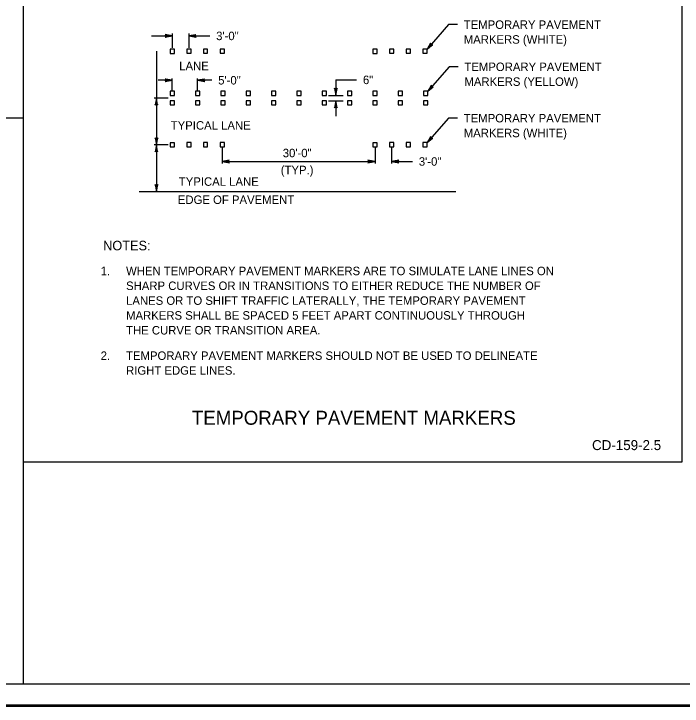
# Model space of a CAD drawing. Extents: x 499940 to 501012, y 499990 to 500649.
# Drawn here: x 500335 to 500650.7, y 499989.5 to 500316.4 of the extents above; entities that cross this region are included whole.
import ezdxf

# ---------------------------------------------------------------- set-up
doc = ezdxf.new("R2010")
doc.units = 0
for name, color, linetype in [('1', 7, 'Continuous'), ('10', 7, 'Continuous'), ('24', 7, 'Continuous'), ('3', 7, 'Continuous'), ('39', 7, 'Continuous'), ('41', 7, 'Continuous'), ('5', 7, 'Continuous'), ('60', 7, 'Continuous')]:
    doc.layers.add(name, color=color, linetype=linetype)

msp = doc.modelspace()

# ---------------------------------------------------------------- linework, layer by layer
at = {"layer": '1'}
for p, q in [((500000, 500000), (500990, 500000)), ((499946.96, 499989.52), (501012.44, 499989.52))]:
    msp.add_line(p, q, dxfattribs=at)
at = {"layer": '10'}
for p, q in [((500339.52, 500000), (500339.52, 500630)), ((500650.61, 500104.92), (500650.61, 500630)), ((500000, 500267.34), (500339.52, 500267.34)), ((500339.52, 500104.92), (500650.61, 500104.92))]:
    msp.add_line(p, q, dxfattribs=at)
at = {"layer": '24'}
for points in [[(500409.84, 500306.02), (500406.51, 500306.61), (500407.31, 500306.02), (500406.53, 500305.45), (500409.84, 500306.02), (500409.62, 500306.02), (500406.61, 500306.57), (500407.37, 500306.02), (500406.67, 500305.49), (500409.5, 500306.01), (500409.39, 500306.02), (500406.81, 500306.48), (500407.39, 500306.02), (500406.79, 500305.57), (500409.34, 500306.02), (500409.23, 500306.01), (500406.97, 500306.41), (500407.41, 500306.02), (500406.96, 500305.62), (500408.9, 500306.01), (500408.72, 500306.01), (500407.14, 500306.33), (500407.45, 500306.03), (500407.12, 500305.7), (500408.68, 500306.02), (500408.51, 500306.03), (500407.32, 500306.24), (500407.55, 500306.01), (500407.3, 500305.78), (500408.34, 500306.02), (500408.18, 500306.04), (500407.46, 500306.18), (500407.58, 500306.02), (500407.39, 500305.84), (500408.09, 500306.02), (500407.62, 500306.13), (500407.69, 500306.01), (500407.49, 500305.88), (500407.97, 500306.01), (500407.67, 500306.08), (500407.79, 500305.98), (500407.65, 500305.92), (500407.79, 500306.02), (500407.72, 500306.03)], [(500417.71, 500306.02), (500421.04, 500305.44), (500420.24, 500306.02), (500421.02, 500306.6), (500417.71, 500306.02), (500417.93, 500306.03), (500420.94, 500305.48), (500420.18, 500306.03), (500420.88, 500306.56), (500418.05, 500306.04), (500418.16, 500306.02), (500420.74, 500305.57), (500420.16, 500306.03), (500420.76, 500306.48), (500418.21, 500306.02), (500418.32, 500306.04), (500420.58, 500305.63), (500420.14, 500306.02), (500420.59, 500306.43), (500418.64, 500306.04), (500418.83, 500306.04), (500420.41, 500305.72), (500420.1, 500306.02), (500420.43, 500306.35), (500418.87, 500306.02), (500419.04, 500306.01), (500420.23, 500305.81), (500420, 500306.04), (500420.25, 500306.27), (500419.21, 500306.02), (500419.37, 500306.01), (500420.09, 500305.87), (500419.97, 500306.03), (500420.16, 500306.21), (500419.46, 500306.02), (500419.92, 500305.91), (500419.86, 500306.04), (500420.06, 500306.17), (500419.58, 500306.04), (500419.88, 500305.96), (500419.75, 500306.06), (500419.9, 500306.13), (500419.75, 500306.03), (500419.83, 500306.02)], [(500530.19, 500299.83), (500532.78, 500301.91), (500531.83, 500301.7), (500531.91, 500302.66), (500530.19, 500299.83), (500530.33, 500300), (500532.69, 500301.87), (500531.79, 500301.66), (500531.86, 500302.53), (500530.4, 500300.09), (500530.48, 500300.16), (500532.5, 500301.78), (500531.78, 500301.65), (500531.83, 500302.38), (500530.52, 500300.2), (500530.58, 500300.29), (500532.34, 500301.7), (500531.77, 500301.63), (500531.76, 500302.22), (500530.78, 500300.53), (500530.91, 500300.67), (500532.17, 500301.63), (500531.75, 500301.6), (500531.72, 500302.05), (500530.94, 500300.68), (500531.06, 500300.81), (500531.98, 500301.56), (500531.67, 500301.54), (500531.66, 500301.87), (500531.16, 500300.94), (500531.28, 500301.05), (500531.85, 500301.49), (500531.65, 500301.51), (500531.65, 500301.77), (500531.33, 500301.12), (500531.71, 500301.4), (500531.57, 500301.43), (500531.61, 500301.66), (500531.39, 500301.22), (500531.64, 500301.4), (500531.49, 500301.37), (500531.54, 500301.52), (500531.51, 500301.35), (500531.57, 500301.39)], [(500409.84, 500285.08), (500406.51, 500285.67), (500407.31, 500285.08), (500406.53, 500284.5), (500409.84, 500285.08), (500409.62, 500285.08), (500406.61, 500285.63), (500407.37, 500285.07), (500406.67, 500284.55), (500409.5, 500285.06), (500409.39, 500285.08), (500406.81, 500285.54), (500407.39, 500285.07), (500406.79, 500284.62), (500409.34, 500285.08), (500409.23, 500285.06), (500406.97, 500285.47), (500407.41, 500285.08), (500406.96, 500284.68), (500408.9, 500285.06), (500408.72, 500285.06), (500407.14, 500285.39), (500407.45, 500285.09), (500407.12, 500284.76), (500408.68, 500285.08), (500408.51, 500285.09), (500407.32, 500285.29), (500407.55, 500285.06), (500407.3, 500284.84), (500408.34, 500285.08), (500408.18, 500285.1), (500407.46, 500285.23), (500407.58, 500285.07), (500407.39, 500284.9), (500408.09, 500285.08), (500407.62, 500285.19), (500407.69, 500285.06), (500407.49, 500284.94), (500407.97, 500285.06), (500407.67, 500285.14), (500407.79, 500285.04), (500407.65, 500284.98), (500407.79, 500285.07), (500407.72, 500285.09)], [(500421.81, 500285.08), (500425.13, 500284.49), (500424.34, 500285.08), (500425.11, 500285.66), (500421.81, 500285.08), (500422.03, 500285.09), (500425.04, 500284.54), (500424.27, 500285.09), (500424.98, 500285.61), (500422.15, 500285.1), (500422.26, 500285.08), (500424.84, 500284.62), (500424.26, 500285.09), (500424.85, 500285.54), (500422.31, 500285.08), (500422.42, 500285.1), (500424.67, 500284.69), (500424.23, 500285.08), (500424.68, 500285.49), (500422.74, 500285.1), (500422.93, 500285.1), (500424.5, 500284.78), (500424.2, 500285.07), (500424.53, 500285.4), (500422.96, 500285.08), (500423.14, 500285.07), (500424.32, 500284.87), (500424.1, 500285.1), (500424.34, 500285.33), (500423.3, 500285.08), (500423.47, 500285.06), (500424.18, 500284.93), (500424.06, 500285.09), (500424.26, 500285.27), (500423.55, 500285.08), (500424.02, 500284.97), (500423.95, 500285.1), (500424.16, 500285.23), (500423.67, 500285.1), (500423.98, 500285.02), (500423.85, 500285.12), (500424, 500285.18), (500423.85, 500285.09), (500423.93, 500285.07)], [(500487.06, 500277.93), (500487.65, 500281.28), (500487.06, 500280.48), (500486.48, 500281.27), (500487.06, 500277.93), (500487.06, 500278.16), (500487.61, 500281.19), (500487.05, 500280.42), (500486.52, 500281.13), (500487.04, 500278.28), (500487.06, 500278.39), (500487.52, 500280.99), (500487.05, 500280.4), (500486.6, 500281), (500487.06, 500278.44), (500487.04, 500278.55), (500487.45, 500280.82), (500487.06, 500280.38), (500486.65, 500280.83), (500487.04, 500278.87), (500487.04, 500279.06), (500487.37, 500280.65), (500487.07, 500280.34), (500486.74, 500280.68), (500487.06, 500279.1), (500487.07, 500279.28), (500487.28, 500280.47), (500487.04, 500280.24), (500486.81, 500280.49), (500487.06, 500279.44), (500487.08, 500279.61), (500487.22, 500280.33), (500487.05, 500280.21), (500486.88, 500280.4), (500487.06, 500279.7), (500487.17, 500280.16), (500487.04, 500280.1), (500486.92, 500280.3), (500487.04, 500279.81), (500487.12, 500280.12), (500487.02, 500279.99), (500486.96, 500280.14), (500487.05, 500279.99), (500487.07, 500280.07)], [(500530.51, 500279.9), (500533.1, 500281.98), (500532.15, 500281.78), (500532.22, 500282.73), (500530.51, 500279.9), (500530.65, 500280.07), (500533.01, 500281.94), (500532.1, 500281.74), (500532.17, 500282.6), (500530.72, 500280.16), (500530.8, 500280.24), (500532.81, 500281.85), (500532.09, 500281.72), (500532.14, 500282.46), (500530.83, 500280.27), (500530.89, 500280.37), (500532.66, 500281.77), (500532.08, 500281.7), (500532.07, 500282.3), (500531.1, 500280.6), (500531.22, 500280.74), (500532.49, 500281.7), (500532.07, 500281.67), (500532.04, 500282.13), (500531.26, 500280.76), (500531.38, 500280.88), (500532.3, 500281.63), (500531.98, 500281.61), (500531.97, 500281.94), (500531.48, 500281.01), (500531.6, 500281.12), (500532.16, 500281.56), (500531.97, 500281.58), (500531.96, 500281.84), (500531.64, 500281.2), (500532.02, 500281.47), (500531.89, 500281.5), (500531.92, 500281.74), (500531.7, 500281.3), (500531.96, 500281.47), (500531.8, 500281.44), (500531.85, 500281.59), (500531.83, 500281.42), (500531.89, 500281.47)], [(500402.34, 500276.65), (500401.75, 500273.33), (500402.34, 500274.12), (500402.92, 500273.35), (500402.34, 500276.65), (500402.35, 500276.43), (500401.8, 500273.42), (500402.35, 500274.19), (500402.87, 500273.48), (500402.36, 500276.31), (500402.34, 500276.2), (500401.88, 500273.62), (500402.35, 500274.2), (500402.8, 500273.61), (500402.34, 500276.15), (500402.36, 500276.04), (500401.95, 500273.79), (500402.34, 500274.23), (500402.74, 500273.78), (500402.36, 500275.72), (500402.36, 500275.53), (500402.03, 500273.96), (500402.33, 500274.26), (500402.66, 500273.93), (500402.34, 500275.5), (500402.33, 500275.32), (500402.13, 500274.14), (500402.36, 500274.36), (500402.58, 500274.12), (500402.34, 500275.16), (500402.32, 500274.99), (500402.19, 500274.28), (500402.35, 500274.4), (500402.52, 500274.2), (500402.34, 500274.91), (500402.23, 500274.44), (500402.36, 500274.51), (500402.48, 500274.3), (500402.36, 500274.79), (500402.28, 500274.48), (500402.38, 500274.61), (500402.44, 500274.47), (500402.35, 500274.61), (500402.33, 500274.53)], [(500487.06, 500275.38), (500486.47, 500272.03), (500487.06, 500272.83), (500487.64, 500272.05), (500487.06, 500275.38), (500487.07, 500275.16), (500486.51, 500272.13), (500487.07, 500272.9), (500487.6, 500272.19), (500487.08, 500275.04), (500487.06, 500274.93), (500486.6, 500272.33), (500487.07, 500272.91), (500487.52, 500272.31), (500487.06, 500274.88), (500487.08, 500274.77), (500486.67, 500272.49), (500487.06, 500272.94), (500487.47, 500272.49), (500487.08, 500274.44), (500487.08, 500274.25), (500486.75, 500272.66), (500487.05, 500272.97), (500487.38, 500272.64), (500487.06, 500274.22), (500487.05, 500274.04), (500486.85, 500272.85), (500487.08, 500273.08), (500487.31, 500272.83), (500487.06, 500273.88), (500487.04, 500273.71), (500486.91, 500272.99), (500487.07, 500273.11), (500487.25, 500272.91), (500487.06, 500273.62), (500486.95, 500273.15), (500487.08, 500273.22), (500487.21, 500273.01), (500487.08, 500273.5), (500487, 500273.2), (500487.1, 500273.32), (500487.16, 500273.18), (500487.07, 500273.32), (500487.05, 500273.25)], [(500402.34, 500254.57), (500402.93, 500257.89), (500402.34, 500257.1), (500401.76, 500257.87), (500402.34, 500254.57), (500402.33, 500254.79), (500402.88, 500257.8), (500402.33, 500257.04), (500401.81, 500257.74), (500402.32, 500254.91), (500402.34, 500255.02), (500402.8, 500257.6), (500402.33, 500257.02), (500401.88, 500257.61), (500402.34, 500255.07), (500402.32, 500255.18), (500402.73, 500257.43), (500402.34, 500256.99), (500401.93, 500257.44), (500402.32, 500255.5), (500402.32, 500255.69), (500402.65, 500257.27), (500402.35, 500256.96), (500402.02, 500257.29), (500402.34, 500255.72), (500402.35, 500255.9), (500402.55, 500257.09), (500402.32, 500256.86), (500402.09, 500257.1), (500402.34, 500256.06), (500402.36, 500256.23), (500402.49, 500256.94), (500402.33, 500256.82), (500402.15, 500257.02), (500402.34, 500256.32), (500402.45, 500256.78), (500402.32, 500256.71), (500402.19, 500256.92), (500402.32, 500256.43), (500402.4, 500256.74), (500402.3, 500256.61), (500402.24, 500256.76), (500402.33, 500256.61), (500402.35, 500256.69)], [(500530.19, 500255.66), (500532.78, 500257.74), (500531.83, 500257.53), (500531.91, 500258.48), (500530.19, 500255.66), (500530.33, 500255.82), (500532.69, 500257.7), (500531.79, 500257.49), (500531.86, 500258.35), (500530.4, 500255.92), (500530.48, 500255.99), (500532.5, 500257.6), (500531.78, 500257.48), (500531.83, 500258.21), (500530.52, 500256.03), (500530.58, 500256.12), (500532.34, 500257.53), (500531.77, 500257.45), (500531.76, 500258.05), (500530.78, 500256.36), (500530.91, 500256.5), (500532.17, 500257.46), (500531.75, 500257.42), (500531.72, 500257.88), (500530.94, 500256.51), (500531.06, 500256.64), (500531.98, 500257.38), (500531.67, 500257.36), (500531.66, 500257.69), (500531.16, 500256.76), (500531.28, 500256.88), (500531.85, 500257.32), (500531.65, 500257.33), (500531.65, 500257.59), (500531.33, 500256.95), (500531.71, 500257.22), (500531.57, 500257.26), (500531.61, 500257.49), (500531.39, 500257.05), (500531.64, 500257.23), (500531.49, 500257.2), (500531.54, 500257.34), (500531.51, 500257.18), (500531.57, 500257.22)], [(500402.34, 500254.57), (500401.75, 500251.24), (500402.34, 500252.04), (500402.92, 500251.26), (500402.34, 500254.57), (500402.35, 500254.35), (500401.8, 500251.34), (500402.35, 500252.1), (500402.87, 500251.4), (500402.36, 500254.23), (500402.34, 500254.12), (500401.88, 500251.54), (500402.35, 500252.12), (500402.8, 500251.52), (500402.34, 500254.07), (500402.36, 500253.96), (500401.95, 500251.7), (500402.34, 500252.14), (500402.74, 500251.69), (500402.36, 500253.63), (500402.36, 500253.45), (500402.03, 500251.87), (500402.33, 500252.18), (500402.66, 500251.85), (500402.34, 500253.41), (500402.33, 500253.24), (500402.13, 500252.05), (500402.36, 500252.28), (500402.58, 500252.03), (500402.34, 500253.07), (500402.32, 500252.91), (500402.19, 500252.19), (500402.35, 500252.31), (500402.52, 500252.12), (500402.34, 500252.82), (500402.23, 500252.35), (500402.36, 500252.42), (500402.48, 500252.22), (500402.36, 500252.7), (500402.28, 500252.4), (500402.38, 500252.52), (500402.44, 500252.38), (500402.35, 500252.52), (500402.33, 500252.45)], [(500433.46, 500246.72), (500436.78, 500246.13), (500435.99, 500246.72), (500436.77, 500247.29), (500433.46, 500246.72), (500433.68, 500246.72), (500436.69, 500246.17), (500435.93, 500246.72), (500436.63, 500247.25), (500433.8, 500246.73), (500433.91, 500246.72), (500436.49, 500246.26), (500435.91, 500246.72), (500436.5, 500247.17), (500433.96, 500246.72), (500434.07, 500246.73), (500436.32, 500246.33), (500435.89, 500246.72), (500436.33, 500247.12), (500434.39, 500246.73), (500434.58, 500246.73), (500436.16, 500246.41), (500435.85, 500246.71), (500436.18, 500247.04), (500434.61, 500246.72), (500434.79, 500246.71), (500435.98, 500246.5), (500435.75, 500246.73), (500436, 500246.96), (500434.95, 500246.72), (500435.12, 500246.7), (500435.83, 500246.56), (500435.72, 500246.72), (500435.91, 500246.9), (500435.21, 500246.72), (500435.67, 500246.61), (500435.61, 500246.73), (500435.81, 500246.86), (500435.32, 500246.73), (500435.63, 500246.66), (500435.5, 500246.76), (500435.65, 500246.82), (500435.5, 500246.72), (500435.58, 500246.71)], [(500505.59, 500246.72), (500502.26, 500247.3), (500503.06, 500246.72), (500502.28, 500246.14), (500505.59, 500246.72), (500505.36, 500246.71), (500502.35, 500247.26), (500503.12, 500246.71), (500502.41, 500246.18), (500505.25, 500246.7), (500505.14, 500246.72), (500502.56, 500247.17), (500503.14, 500246.71), (500502.54, 500246.26), (500505.08, 500246.72), (500504.97, 500246.7), (500502.72, 500247.11), (500503.16, 500246.72), (500502.71, 500246.31), (500504.65, 500246.7), (500504.47, 500246.7), (500502.89, 500247.02), (500503.19, 500246.73), (500502.86, 500246.4), (500504.43, 500246.72), (500504.25, 500246.73), (500503.07, 500246.93), (500503.3, 500246.7), (500503.05, 500246.47), (500504.09, 500246.72), (500503.92, 500246.73), (500503.21, 500246.87), (500503.33, 500246.71), (500503.13, 500246.53), (500503.84, 500246.72), (500503.37, 500246.83), (500503.44, 500246.7), (500503.24, 500246.57), (500503.72, 500246.7), (500503.42, 500246.78), (500503.54, 500246.68), (500503.4, 500246.62), (500503.54, 500246.71), (500503.47, 500246.73)], [(500513.46, 500246.72), (500516.78, 500246.13), (500515.99, 500246.72), (500516.77, 500247.29), (500513.46, 500246.72), (500513.68, 500246.72), (500516.69, 500246.17), (500515.93, 500246.72), (500516.63, 500247.25), (500513.8, 500246.73), (500513.91, 500246.72), (500516.49, 500246.26), (500515.91, 500246.72), (500516.5, 500247.17), (500513.96, 500246.72), (500514.07, 500246.73), (500516.32, 500246.33), (500515.89, 500246.72), (500516.33, 500247.12), (500514.39, 500246.73), (500514.58, 500246.73), (500516.16, 500246.41), (500515.85, 500246.71), (500516.18, 500247.04), (500514.61, 500246.72), (500514.79, 500246.71), (500515.98, 500246.5), (500515.75, 500246.73), (500516, 500246.96), (500514.95, 500246.72), (500515.12, 500246.7), (500515.83, 500246.56), (500515.72, 500246.72), (500515.91, 500246.9), (500515.21, 500246.72), (500515.67, 500246.61), (500515.61, 500246.73), (500515.81, 500246.86), (500515.32, 500246.73), (500515.63, 500246.66), (500515.5, 500246.76), (500515.65, 500246.82), (500515.5, 500246.72), (500515.58, 500246.71)], [(500402.34, 500232.48), (500402.93, 500235.8), (500402.34, 500235.01), (500401.76, 500235.79), (500402.34, 500232.48), (500402.33, 500232.7), (500402.88, 500235.71), (500402.33, 500234.95), (500401.81, 500235.65), (500402.32, 500232.82), (500402.34, 500232.93), (500402.8, 500235.51), (500402.33, 500234.93), (500401.88, 500235.53), (500402.34, 500232.98), (500402.32, 500233.09), (500402.73, 500235.35), (500402.34, 500234.91), (500401.93, 500235.36), (500402.32, 500233.41), (500402.32, 500233.6), (500402.65, 500235.18), (500402.35, 500234.87), (500402.02, 500235.2), (500402.34, 500233.63), (500402.35, 500233.81), (500402.55, 500235), (500402.32, 500234.77), (500402.09, 500235.02), (500402.34, 500233.98), (500402.36, 500234.14), (500402.49, 500234.85), (500402.33, 500234.74), (500402.15, 500234.93), (500402.34, 500234.23), (500402.45, 500234.69), (500402.32, 500234.63), (500402.19, 500234.83), (500402.32, 500234.35), (500402.4, 500234.65), (500402.3, 500234.52), (500402.24, 500234.67), (500402.33, 500234.52), (500402.35, 500234.6)]]:
    msp.add_lwpolyline(points, dxfattribs=at)
at = {"layer": '3'}
msp.add_line((500394.18, 500232.48), (500543.77, 500232.48), dxfattribs=at)
at = {"layer": '41'}
msp.add_lwpolyline([(499939.98, 499990.18), (501000.54, 499990.18), (501000.54, 500649.16), (499939.98, 500649.16)], close=True, dxfattribs=at)
at = {"layer": '5'}
for p, q in [((500400.06, 500306.02), (500409.84, 500306.02)), ((500409.84, 500307.16), (500409.84, 500300.35)), ((500417.71, 500307.16), (500417.71, 500300.35)), ((500417.71, 500306.02), (500427.54, 500306.02)), ((500402.34, 500298.74), (500402.34, 500276.65)), ((500409.84, 500285.08), (500403.14, 500285.08)), ((500409.84, 500280.47), (500409.84, 500285.94)), ((500421.81, 500280.47), (500421.81, 500285.94)), ((500428.5, 500285.08), (500421.81, 500285.08)), ((500487.06, 500285.26), (500487.06, 500277.93)), ((500487.06, 500285.26), (500496.89, 500285.26)), ((500407.92, 500276.65), (500401.22, 500276.65)), ((500402.34, 500276.65), (500402.34, 500254.57)), ((500483.63, 500277.93), (500490.49, 500277.93)), ((500483.63, 500275.38), (500490.49, 500275.38)), ((500487.06, 500275.38), (500487.06, 500268.06)), ((500407.92, 500254.57), (500401.22, 500254.57)), ((500402.34, 500254.57), (500402.34, 500232.48)), ((500433.46, 500253.1), (500433.46, 500245.77)), ((500505.59, 500253.1), (500505.59, 500245.77)), ((500513.46, 500253.1), (500513.46, 500245.77)), ((500433.46, 500246.72), (500505.59, 500246.72)), ((500513.46, 500246.72), (500523.29, 500246.72))]:
    msp.add_line(p, q, dxfattribs=at)
for points in [[(500544.52, 500311.35), (500540.28, 500311.35), (500530.19, 500299.83)], [(500544.83, 500291.43), (500540.6, 500291.43), (500530.51, 500279.9)], [(500544.52, 500267.18), (500540.28, 500267.18), (500530.19, 500255.66)]]:
    msp.add_lwpolyline(points, dxfattribs=at)
at = {"layer": '60'}
for points in [[(500408.85, 500297.76), (500410.82, 500297.76), (500410.82, 500299.73), (500408.85, 500299.73)], [(500416.73, 500297.86), (500418.7, 500297.86), (500418.7, 500299.83), (500416.73, 500299.83)], [(500424.57, 500297.86), (500426.54, 500297.86), (500426.54, 500299.83), (500424.57, 500299.83)], [(500432.48, 500297.86), (500434.44, 500297.86), (500434.44, 500299.83), (500432.48, 500299.83)], [(500504.6, 500297.76), (500506.57, 500297.76), (500506.57, 500299.73), (500504.6, 500299.73)], [(500512.48, 500297.86), (500514.44, 500297.86), (500514.44, 500299.83), (500512.48, 500299.83)], [(500520.32, 500297.86), (500522.29, 500297.86), (500522.29, 500299.83), (500520.32, 500299.83)], [(500528.22, 500297.86), (500530.19, 500297.86), (500530.19, 500299.83), (500528.22, 500299.83)], [(500408.85, 500277.93), (500410.82, 500277.93), (500410.82, 500279.9), (500408.85, 500279.9)], [(500420.82, 500277.93), (500422.79, 500277.93), (500422.79, 500279.9), (500420.82, 500279.9)], [(500432.79, 500277.93), (500434.76, 500277.93), (500434.76, 500279.9), (500432.79, 500279.9)], [(500444.76, 500277.93), (500446.73, 500277.93), (500446.73, 500279.9), (500444.76, 500279.9)], [(500456.73, 500277.93), (500458.7, 500277.93), (500458.7, 500279.9), (500456.73, 500279.9)], [(500468.7, 500277.93), (500470.66, 500277.93), (500470.66, 500279.9), (500468.7, 500279.9)], [(500480.66, 500277.93), (500482.63, 500277.93), (500482.63, 500279.9), (500480.66, 500279.9)], [(500492.63, 500277.93), (500494.6, 500277.93), (500494.6, 500279.9), (500492.63, 500279.9)], [(500504.6, 500277.93), (500506.57, 500277.93), (500506.57, 500279.9), (500504.6, 500279.9)], [(500516.57, 500277.93), (500518.54, 500277.93), (500518.54, 500279.9), (500516.57, 500279.9)], [(500528.54, 500277.93), (500530.51, 500277.93), (500530.51, 500279.9), (500528.54, 500279.9)], [(500408.85, 500273.41), (500410.82, 500273.41), (500410.82, 500275.38), (500408.85, 500275.38)], [(500420.82, 500273.41), (500422.79, 500273.41), (500422.79, 500275.38), (500420.82, 500275.38)], [(500432.79, 500273.41), (500434.76, 500273.41), (500434.76, 500275.38), (500432.79, 500275.38)], [(500444.76, 500273.41), (500446.73, 500273.41), (500446.73, 500275.38), (500444.76, 500275.38)], [(500456.73, 500273.41), (500458.7, 500273.41), (500458.7, 500275.38), (500456.73, 500275.38)], [(500468.7, 500273.41), (500470.66, 500273.41), (500470.66, 500275.38), (500468.7, 500275.38)], [(500480.66, 500273.41), (500482.63, 500273.41), (500482.63, 500275.38), (500480.66, 500275.38)], [(500492.63, 500273.41), (500494.6, 500273.41), (500494.6, 500275.38), (500492.63, 500275.38)], [(500504.6, 500273.41), (500506.57, 500273.41), (500506.57, 500275.38), (500504.6, 500275.38)], [(500516.57, 500273.41), (500518.54, 500273.41), (500518.54, 500275.38), (500516.57, 500275.38)], [(500528.54, 500273.41), (500530.51, 500273.41), (500530.51, 500275.38), (500528.54, 500275.38)], [(500408.85, 500253.58), (500410.82, 500253.58), (500410.82, 500255.55), (500408.85, 500255.55)], [(500416.73, 500253.69), (500418.7, 500253.69), (500418.7, 500255.66), (500416.73, 500255.66)], [(500424.57, 500253.69), (500426.54, 500253.69), (500426.54, 500255.66), (500424.57, 500255.66)], [(500432.48, 500253.69), (500434.44, 500253.69), (500434.44, 500255.66), (500432.48, 500255.66)], [(500504.6, 500253.58), (500506.57, 500253.58), (500506.57, 500255.55), (500504.6, 500255.55)], [(500512.48, 500253.69), (500514.44, 500253.69), (500514.44, 500255.66), (500512.48, 500255.66)], [(500520.32, 500253.69), (500522.29, 500253.69), (500522.29, 500255.66), (500520.32, 500255.66)], [(500528.22, 500253.69), (500530.19, 500253.69), (500530.19, 500255.66), (500528.22, 500255.66)]]:
    msp.add_lwpolyline(points, close=True, dxfattribs=at)

# ---------------------------------------------------------------- texts
at = {"layer": '3'}
for s, p in [('TEMPORARY PAVEMENT', (500547.52, 500309.35)), ('3\'-0"', (500430.54, 500304.02)), ('MARKERS (WHITE)', (500547.52, 500302.35)), ('LANE', (500413.1, 500289.84)), ('TEMPORARY PAVEMENT', (500547.83, 500289.43)), ('5\'-0"', (500431.5, 500283.08)), ('6"', (500499.89, 500283.26)), ('MARKERS (YELLOW)', (500547.83, 500282.43)), ('TEMPORARY PAVEMENT', (500547.52, 500265.18)), ('TYPICAL LANE', (500409.11, 500261.76)), ('MARKERS (WHITE)', (500547.52, 500258.18)), ('30\'-0"', (500462.01, 500248.72)), ('3\'-0"', (500526.29, 500244.72)), ('(TYP.)', (500461.08, 500240.72)), ('TYPICAL LANE', (500412.92, 500235.24)), ('EDGE OF PAVEMENT', (500412.45, 500226.66)), ('1.', (500376, 500193.03)), ('WHEN TEMPORARY PAVEMENT MARKERS ARE TO SIMULATE LANE LINES ON', (500388, 500193.03)), ('SHARP CURVES OR IN TRANSITIONS TO EITHER REDUCE THE NUMBER OF', (500388, 500186.03)), ('LANES OR TO SHIFT TRAFFIC LATERALLY, THE TEMPORARY PAVEMENT', (500388, 500179.03)), ('MARKERS SHALL BE SPACED 5 FEET APART CONTINUOUSLY THROUGH', (500388, 500172.03)), ('THE CURVE OR TRANSITION AREA.', (500388, 500165.03)), ('2.', (500376, 500153.03)), ('TEMPORARY PAVEMENT MARKERS SHOULD NOT BE USED TO DELINEATE', (500388, 500153.03)), ('RIGHT EDGE LINES.', (500388, 500146.03))]:
    msp.add_text(s, height=4, dxfattribs=at).set_placement(p)
at = {"layer": '39'}
msp.add_text('NOTES:', height=4.5, dxfattribs=at).set_placement((500377.16, 500204.78))
at = {"layer": '5'}
for s, height, p in [('TEMPORARY PAVEMENT MARKERS', 6.6001, (500419.08, 500122.39)), ('CD-159-2.5', 4.724, (500608.11, 500110.43))]:
    msp.add_text(s, height=height, dxfattribs=at).set_placement(p)

doc.saveas('drawing.dxf')
